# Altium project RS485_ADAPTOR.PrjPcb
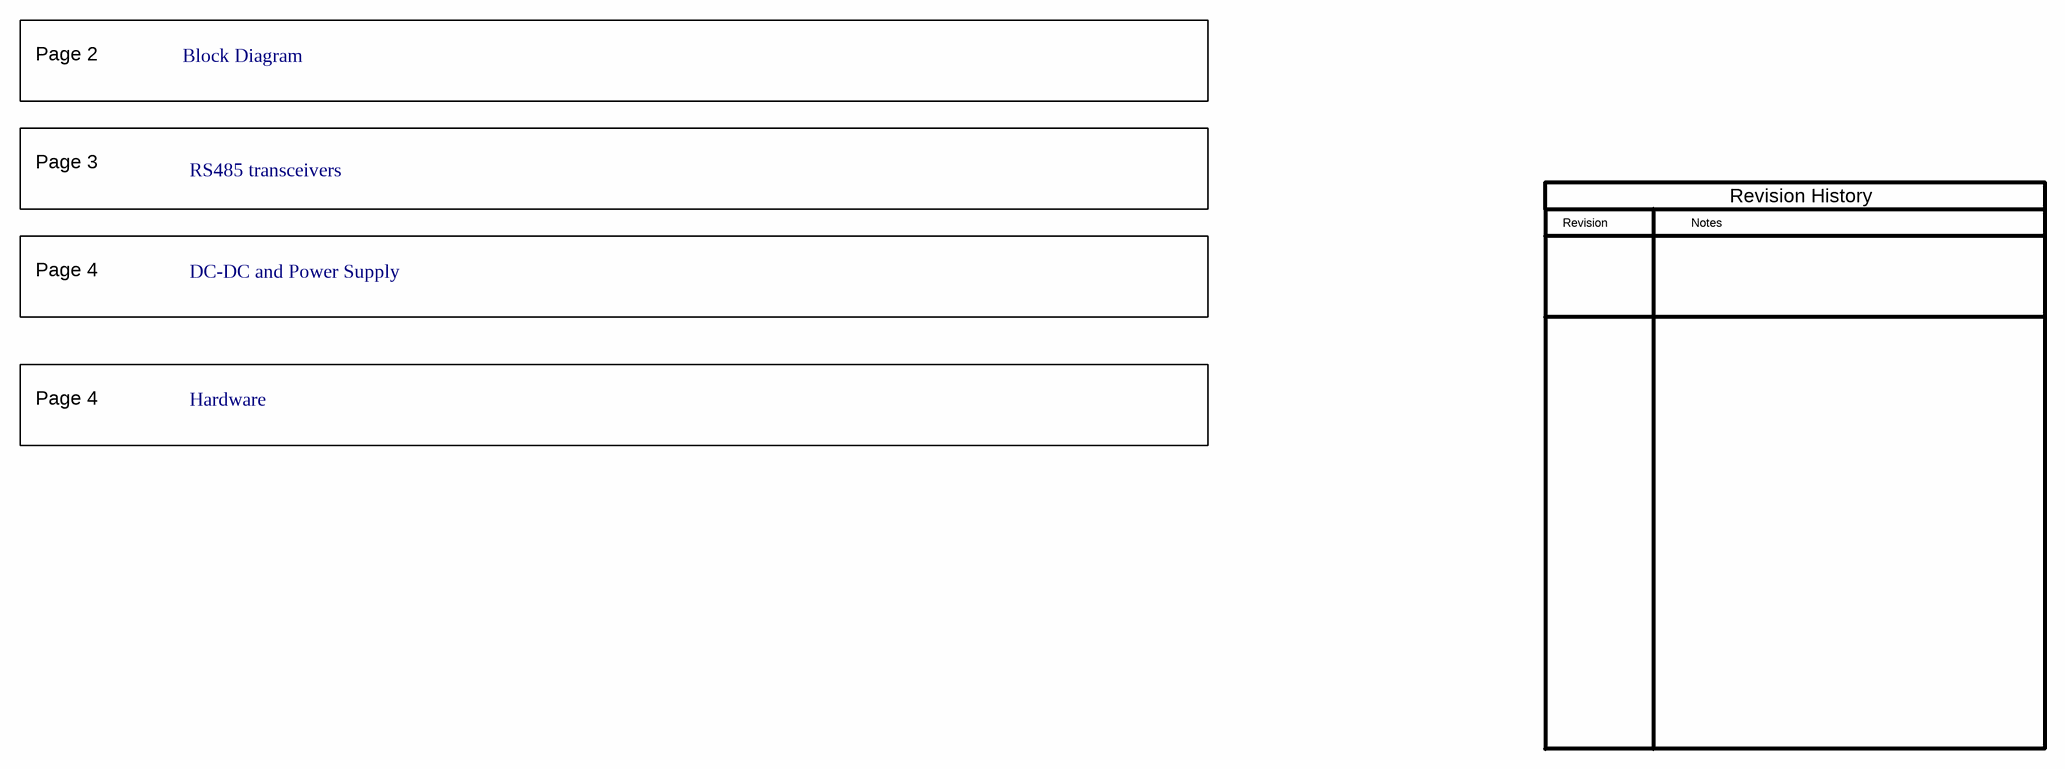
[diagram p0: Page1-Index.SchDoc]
TechSupport: http://www.ti.com/support; SCH_Rev: E2; PRJ_Title: RS485_COMMS; PRJ_Number: TIDA-00308; PRJ_Engineer: Sreenivasa Kallikuppa; PRJ_Customer: Public Release; PCB_Rev: E2; CopyrightYear: 2014
5 sheets, 112 parts. Net scope: flat (ports and power ports of the same name join across sheets).
Board file: RS485_ADAPTOR_E2.PcbDoc
Sheets:
  Page1-Index.SchDoc
  Page2 Block Diagram.SchDoc
  Page3-RS485 Transceivers.SchDoc
  Page4-DC-DC and Power supply.SchDoc
  Page5-Hardware.SchDoc

## Sheet Page1-Index.SchDoc
size 431 x 279 mm; Date: Not shown in title block; ApprovedBy: Not shown in title block; CheckedBy: Not shown in title block; Author: Not shown in title block; CompanyName: Not shown in title block; Engineer: Not shown in title block; Organization: Not shown in title block; Address1: Not shown in title block; Address2: Not shown in title block; Address3: Not shown in title block; Address4: Not shown in title block; DocumentNumber: 1; Revision: Use project parameter SCH_Rev; SheetNumber: 1; SheetTotal: 5; PageSetup: Record=PageOptions|CenterHorizontal=True|CenterVertical=True|PrintScale=0.62|XCorrection=1.00|YCorrection=1.00|PrintKind=0|BorderSize=5000000|LeftOffset=0|BottomOffset=0|Orientation=2|PaperLength=1000|PaperWidth=1000|Scale=100|PaperSource=15|PrintQuality=600|MediaType=1|DitherType=10|PaperKind=Letter|PrintScaleMode=1

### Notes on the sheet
- Page 2
- Block Diagram
- Page 3
- RS485 transceivers
- Revision
- Notes
- Revision History
- Page 4
- DC-DC and Power Supply
- Hardware

## Sheet Page2 Block Diagram.SchDoc
size 431 x 279 mm; Date: Not shown in title block; ApprovedBy: Not shown in title block; CheckedBy: Not shown in title block; Author: Not shown in title block; CompanyName: Not shown in title block; Engineer: Not shown in title block; Organization: Not shown in title block; Address1: Not shown in title block; Address2: Not shown in title block; Address3: Not shown in title block; Address4: Not shown in title block; DocumentNumber: 2; Revision: Use project parameter SCH_Rev; SheetNumber: 2; SheetTotal: 5; PageSetup: Record=PageOptions|CenterHorizontal=True|CenterVertical=True|PrintScale=1.00|XCorrection=1.00|YCorrection=1.00|PrintKind=0|BorderSize=5000000|LeftOffset=0|BottomOffset=0|Orientation=2|PaperLength=1000|PaperWidth=1000|Scale=100|PaperSource=15|PrintQuality=600|MediaType=1|DitherType=10|PaperKind=Letter|PrintScaleMode=1
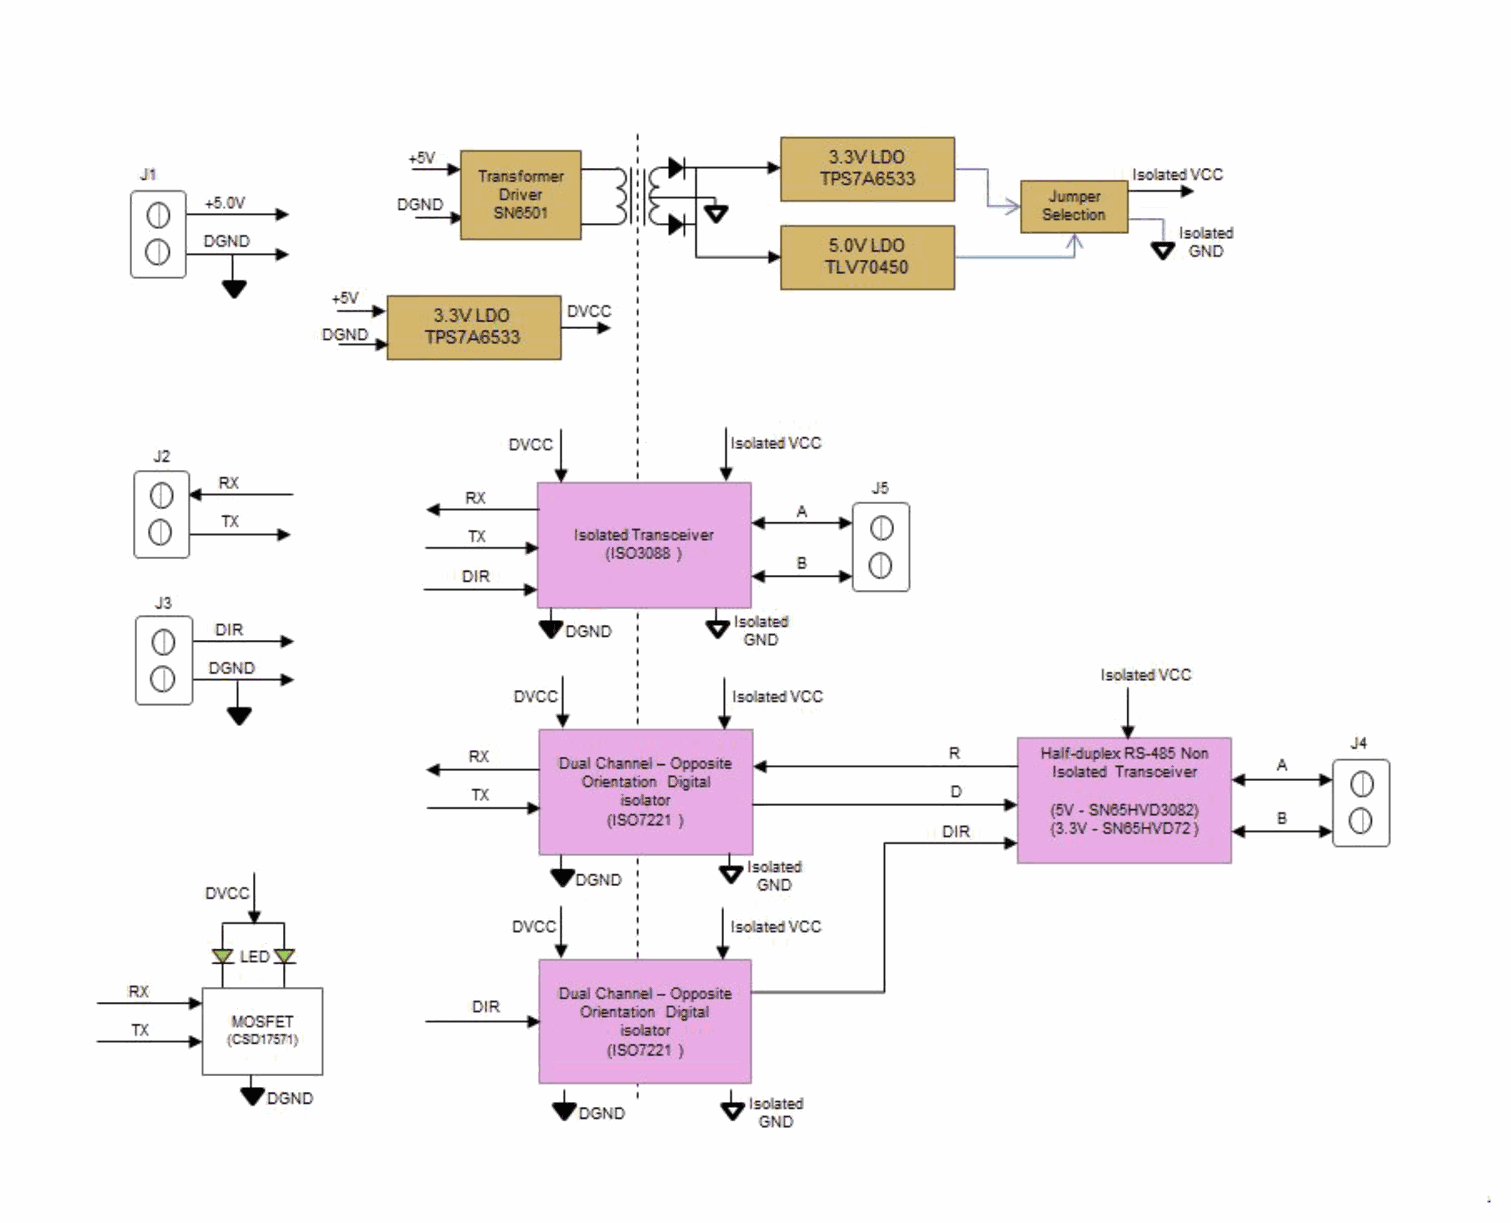
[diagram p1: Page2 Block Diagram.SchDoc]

## Sheet Page3-RS485 Transceivers.SchDoc
size 431 x 279 mm; Date: Not shown in title block; ApprovedBy: Not shown in title block; CheckedBy: Not shown in title block; Author: Not shown in title block; CompanyName: Not shown in title block; Engineer: Not shown in title block; Organization: Not shown in title block; Address1: Not shown in title block; Address2: Not shown in title block; Address3: Not shown in title block; Address4: Not shown in title block; DocumentNumber: 3; Revision: Use project parameter SCH_Rev; SheetNumber: 3; SheetTotal: 5; PageSetup: Record=PageOptions|CenterHorizontal=True|CenterVertical=True|PrintScale=0.62|XCorrection=1.00|YCorrection=1.00|PrintKind=0|BorderSize=5000000|LeftOffset=0|BottomOffset=0|Orientation=2|PaperLength=1000|PaperWidth=1000|Scale=100|PaperSource=15|PrintQuality=600|MediaType=1|DitherType=10|PaperKind=Letter|PrintScaleMode=1
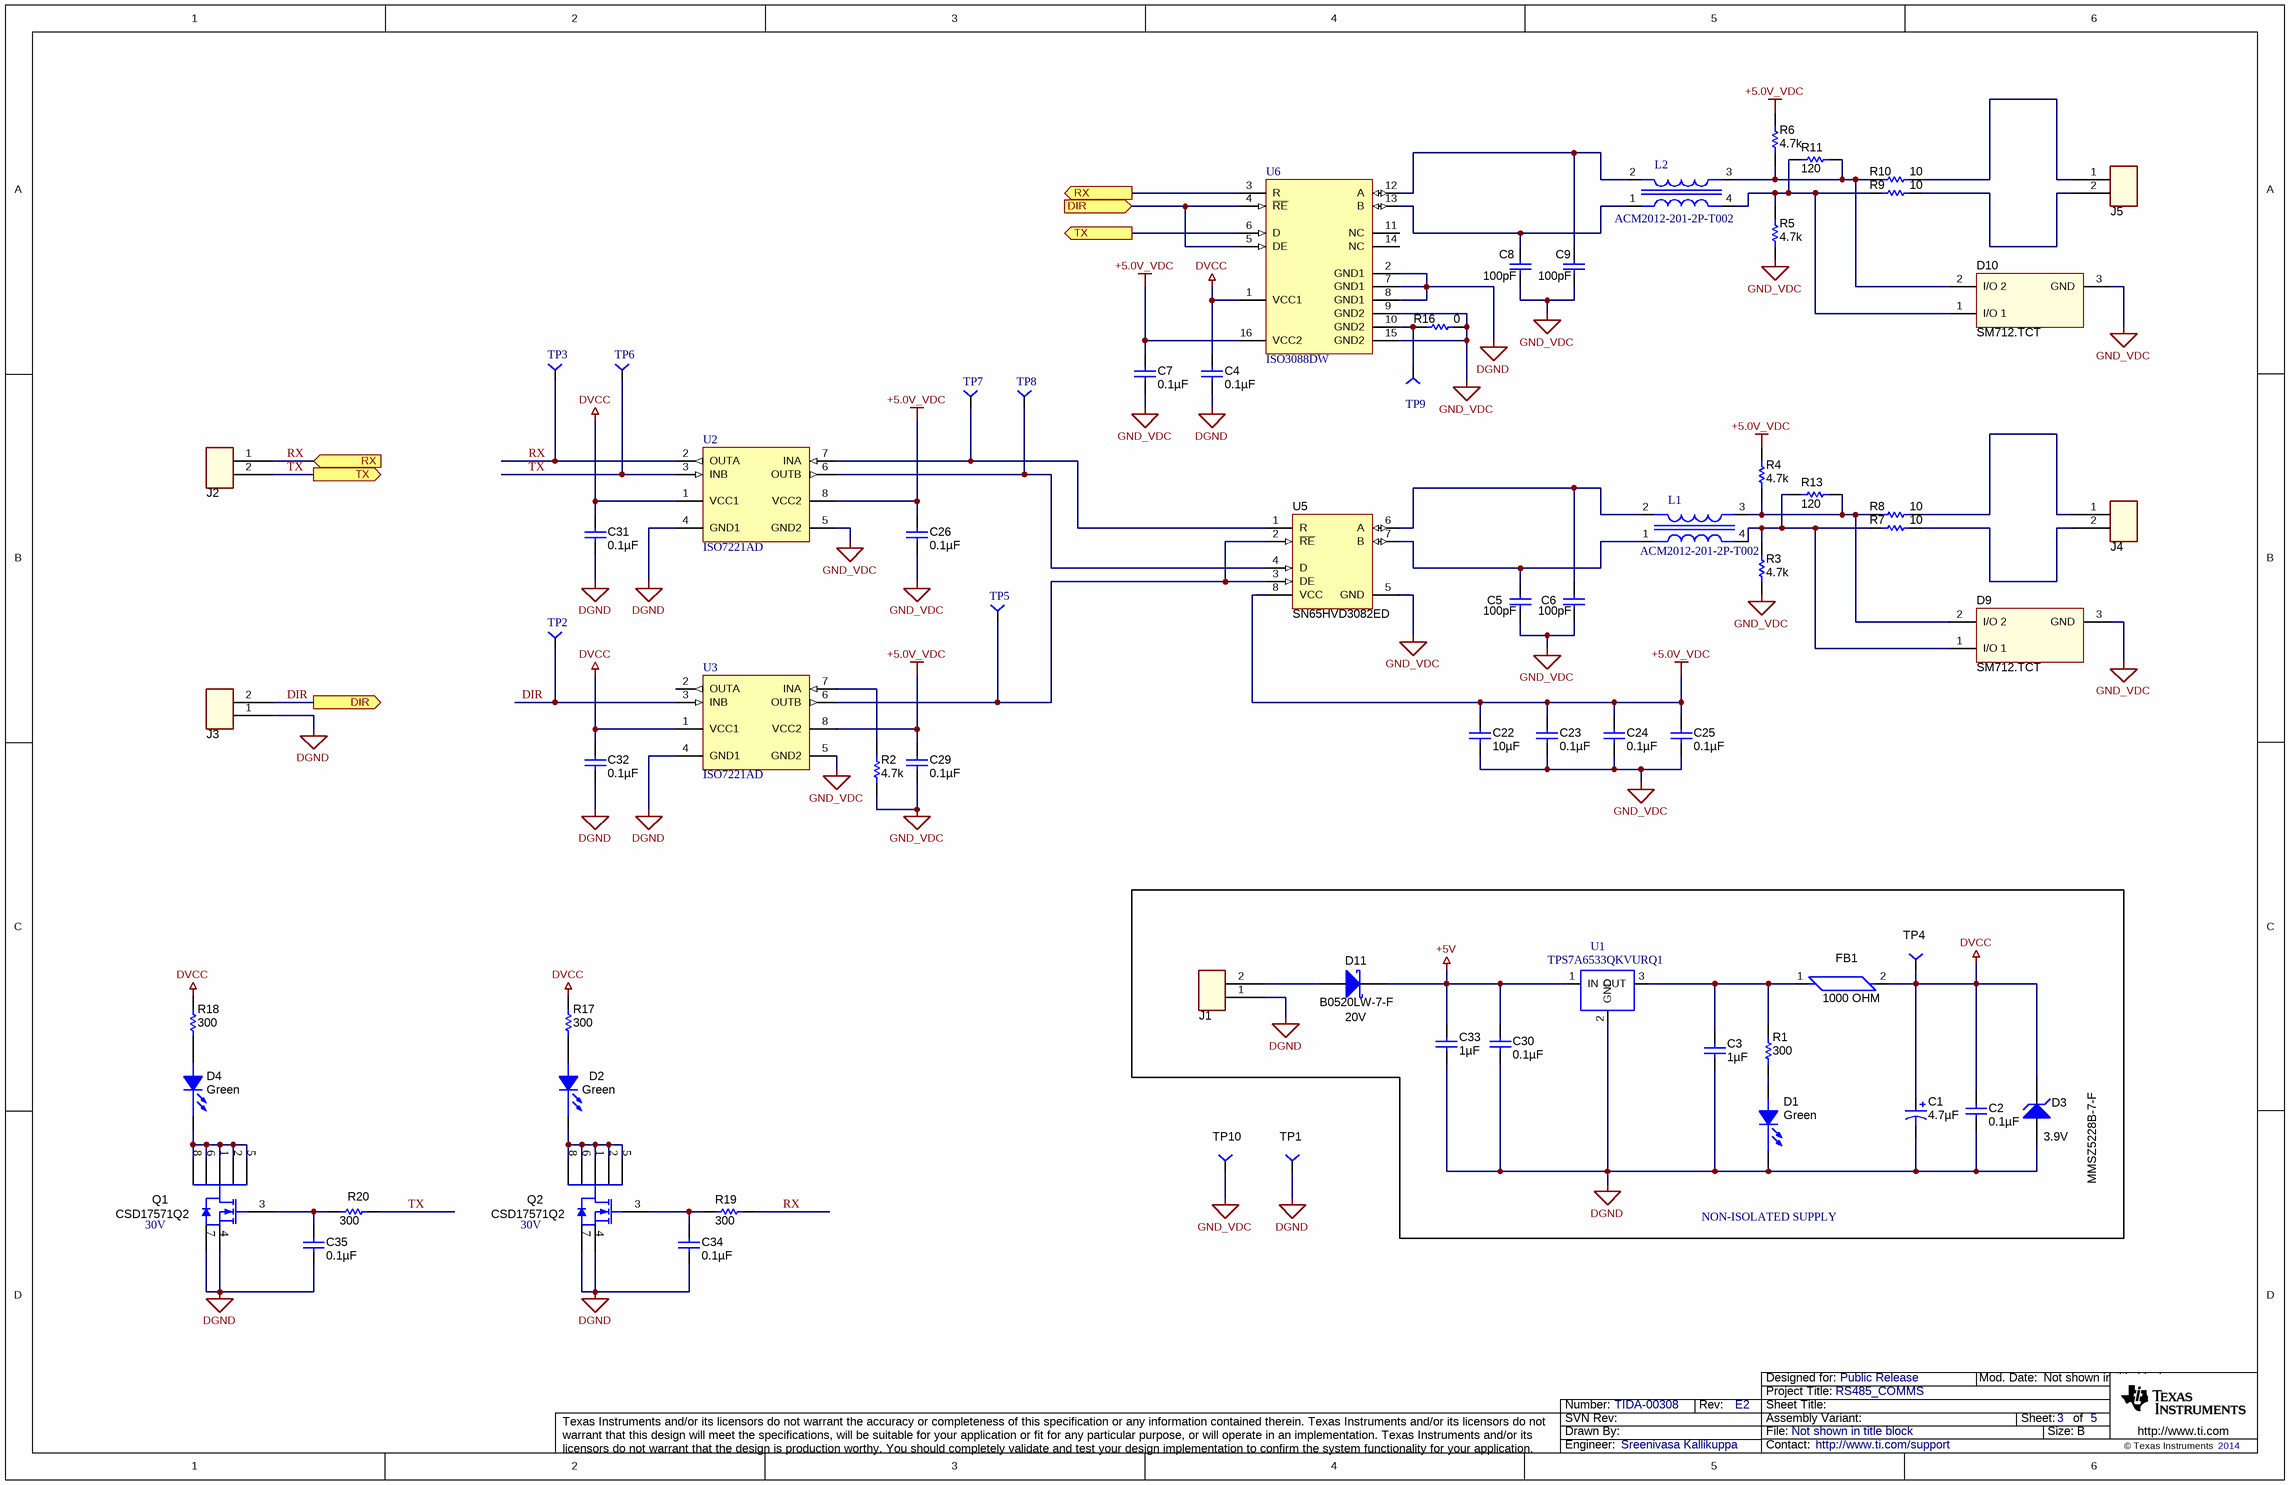
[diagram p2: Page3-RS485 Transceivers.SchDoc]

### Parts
C1  ValueDisplayed: 4.7µF  [6032-28]  (hidden comment: 293D475X9035C2TE3)
C2  ValueDisplayed: 0.1µF  [0603]  (hidden comment: C0603C104K5RACTU)
C3  ValueDisplayed: 1µF  [0603]  (hidden comment: C1608X7R1C105K)
C4  ValueDisplayed: 0.1µF  [0805_HV]  (hidden comment: 08055C104KAT2A)
C5  ValueDisplayed: 100pF  [0805_HV]  (hidden comment: 08055A101JAT2A)
C6  ValueDisplayed: 100pF  [0805_HV]  (hidden comment: 08055A101JAT2A)
C7  ValueDisplayed: 0.1µF  [0805_HV]  (hidden comment: 08055C104KAT2A)
C8  ValueDisplayed: 100pF  [0805_HV]  (hidden comment: 08055A101JAT2A)
C9  ValueDisplayed: 100pF  [0805_HV]  (hidden comment: 08055A101JAT2A)
C22  ValueDisplayed: 10µF  [0603]  (hidden comment: C0603C106M9PACTU)
C23  ValueDisplayed: 0.1µF  [0603]  (hidden comment: 06033C104JAT2A)
C24  ValueDisplayed: 0.1µF  [0603]  (hidden comment: 06033C104JAT2A)
C25  ValueDisplayed: 0.1µF  [0603]  (hidden comment: 06033C104JAT2A)
C26  ValueDisplayed: 0.1µF  [0805_HV]  (hidden comment: 08055C104KAT2A)
C29  ValueDisplayed: 0.1µF  [0805_HV]  (hidden comment: 08055C104KAT2A)
C30  ValueDisplayed: 0.1µF  [0603]  (hidden comment: C0603C104K5RACTU)
C31  ValueDisplayed: 0.1µF  [0805_HV]  (hidden comment: 08055C104KAT2A)
C32  ValueDisplayed: 0.1µF  [0805_HV]  (hidden comment: 08055C104KAT2A)
C33  ValueDisplayed: 1µF  [0603]  (hidden comment: C1608X7R1C105K)
C34  ValueDisplayed: 0.1µF  [0603]  (hidden comment: 06033C104JAT2A)
C35  ValueDisplayed: 0.1µF  [0603]  (hidden comment: 06033C104JAT2A)
D1  value Green  [LED0603AA]  (hidden comment: LED_LG L29K-G2J1-24-Z)
D2  value Green  [LED0603AA]  (hidden comment: LED_LG L29K-G2J1-24-Z)
D3  MMSZ5228B-7-F  value 3.9V  [sod-123]
D4  value Green  [LED0603AA]  (hidden comment: LED_LG L29K-G2J1-24-Z)
D9  SM712.TCT  [SM712.TCT]
D10  SM712.TCT  [SM712.TCT]
D11  B0520LW-7-F  value 20V  [SOD-123]
FB1  1000 OHM  [0603]
J1  CON-OSTVN02A150  [CN2_MTB_P100_PD80_D1.1_S5.54X6.5_STACK]  (value not drawn)
J2  CON-OSTVN02A150  [CN2_MTB_P100_PD80_D1.1_S5.54X6.5_STACK]  (value not drawn)
J3  CON-OSTVN02A150  [CN2_MTB_P100_PD80_D1.1_S5.54X6.5_STACK]  (value not drawn)
J4  CON-OSTVN02A150  [CN2_MTB_P100_PD80_D1.1_S5.54X6.5_STACK]  (value not drawn)
J5  CON-OSTVN02A150  [CN2_MTB_P100_PD80_D1.1_S5.54X6.5_STACK]  (value not drawn)
L1  ACM2012-201-2P-T002  [IND_0805-4P]
L2  ACM2012-201-2P-T002  [IND_0805-4P]
Q1  CSD17571Q2  value 30V  [SON_CSD17571Q2]
Q2  CSD17571Q2  value 30V  [SON_CSD17571Q2]
R1  value 300  [0603]  (hidden comment: CRCW0603300RJNEA)
R2  value 4.7k  [0603]  (hidden comment: CRCW06034K70JNEA)
R3  value 4.7k  [0603]  (hidden comment: CRCW06034K70JNEA)
R4  value 4.7k  [0603]  (hidden comment: CRCW06034K70JNEA)
R5  value 4.7k  [0603]  (hidden comment: CRCW06034K70JNEA)
R6  value 4.7k  [0603]  (hidden comment: CRCW06034K70JNEA)
R7  value 10  [2512M]  (hidden comment: ERJ-1TYJ100U)
R8  value 10  [2512M]  (hidden comment: ERJ-1TYJ100U)
R9  value 10  [2512M]  (hidden comment: ERJ-1TYJ100U)
R10  value 10  [2512M]  (hidden comment: ERJ-1TYJ100U)
R11  value 120  [1206]  (hidden comment: RC1206FR-07120RL)
R13  value 120  [1206]  (hidden comment: RC1206FR-07120RL)
R16  value 0  [0603]  (hidden comment: CRCW06030000Z0EA)
R17  value 300  [0603]  (hidden comment: CRCW0603300RJNEA)
R18  value 300  [0603]  (hidden comment: CRCW0603300RJNEA)
R19  value 300  [0603]  (hidden comment: CRCW0603300RJNEA)
R20  value 300  [0603]  (hidden comment: CRCW0603300RJNEA)
TP1  TP-040_RND  [TP-040_RND]  (value not drawn)
TP2  TP-040_RND  [TP-040_RND]  (value not drawn)
TP3  TP-040_RND  [TP-040_RND]  (value not drawn)
TP4  TP-040_RND  [TP-040_RND]  (value not drawn)
TP5  TP-040_RND  [TP-040_RND]  (value not drawn)
TP6  TP-040_RND  [TP-040_RND]  (value not drawn)
TP7  TP-040_RND  [TP-040_RND]  (value not drawn)
TP8  TP-040_RND  [TP-040_RND]  (value not drawn)
TP9  TP-040_RND  [TP-040_RND]  (value not drawn)
TP10  TP-040_RND  [TP-040_RND]  (value not drawn)
U1  TPS7A6533QKVURQ1  [KVU_1]
U2  ISO7221AD  [D0008A_N]
U3  ISO7221AD  [D0008A_N]
U5  SN65HVD3082ED  [D0008A_N]
U6  ISO3088DW  [DW0016A_N]

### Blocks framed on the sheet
NON-ISOLATED SUPPLY: C1-C3 C30 C33 D1 D3 D11 FB1 J1 R1 TP4 U1

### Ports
DIR (in), DIR (out), RX (in), RX (out), TX (out)

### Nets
+5.0V_VDC: C7.1 C22.1 C23.1 C24.1 C25.1 C26.1 C29.1 R4.2 R6.2 U2.8(VCC2) U3.8(VCC2) U5.8(VCC) U6.16(VCC2)
+5V: C30.1 C33.1 D11.1(K) U1.1(IN)
DGND: C1.2(-) C2.2 C3.2 C4.2 C30.2 C31.2 C32.2 C33.2 C34.2 C35.2 D1.1(C) D3.2(A) J1.1 J3.1 Q1.4(S) Q1.7(S) Q2.4(S) Q2.7(S) TP1.1 U1.2(GND) U2.4(GND1) U3.4(GND1) U6.2(GND1) U6.7(GND1) U6.8(GND1)
DVCC: C1.1(+) C2.1 C4.1 C31.1 C32.1 D3.1(K) FB1.2 R17.2 R18.2 TP4.1 U2.1(VCC1) U3.1(VCC1) U6.1(VCC1)
GND_VDC: C5.2 C6.2 C7.2 C8.2 C9.2 C22.2 C23.2 C24.2 C25.2 C26.2 C29.2 D9.3(GND) D10.3(GND) R2.1 R3.1 R5.1 R16.2 TP10.1 U2.5(GND2) U3.5(GND2) U5.5(GND) U6.9(GND2) U6.15(GND2)
DIR: J3.2 TP2.1 U3.3(INB) U6.4(~{RE}) U6.5(DE) ; port DIR
RX: J2.1 R19.1 TP3.1 U2.2(OUTA) U6.3(R) ; port RX
TX: J2.2 R20.1 TP6.1 U2.3(INB) U6.6(D) ; port TX
NetC3_1: C3.1 FB1.1 R1.2 U1.3(OUT)
NetC5_1: C5.1 L1.1 U5.7(B)
NetC6_1: C6.1 L1.2 U5.6(A)
NetC8_1: C8.1 L2.1 U6.13(B)
NetC9_1: C9.1 L2.2 U6.12(A)
NetC34_1: C34.1 Q2.3(G) R19.2
NetC35_1: C35.1 Q1.3(G) R20.2
NetD1_2: D1.2(A) R1.1
NetD2_1: D2.1(C) Q2.1(D) Q2.2(D) Q2.5(D) Q2.6(D) Q2.8(D)
NetD2_2: D2.2(A) R17.1
NetD4_1: D4.1(C) Q1.1(D) Q1.2(D) Q1.5(D) Q1.6(D) Q1.8(D)
NetD4_2: D4.2(A) R18.1
NetD9_1: D9.1(I/O_1) L1.4 R3.2 R7.1 R13.2
NetD9_2: D9.2(I/O_2) L1.3 R4.1 R8.1 R13.1
NetD10_1: D10.1(I/O_1) L2.4 R5.2 R9.1 R11.2
NetD10_2: D10.2(I/O_2) L2.3 R6.1 R10.1 R11.1
NetD11_2: D11.2(A) J1.2
NetJ4_1: J4.1 R8.2
NetJ4_2: J4.2 R7.2
NetJ5_1: J5.1 R10.2
NetJ5_2: J5.2 R9.2
NetR2_2: R2.2 U3.7(INA)
NetR16_1: R16.1 TP9.1 U6.10(GND2)
NetTP5_1: TP5.1 U3.6(OUTB) U5.2(~{RE}) U5.3(DE)
NetTP7_1: TP7.1 U2.7(INA) U5.1(R)
NetTP8_1: TP8.1 U2.6(OUTB) U5.4(D)

Not connected (* = marked no-connect by the designer): U3 2(OUTA); U6 11(NC) 14(NC)

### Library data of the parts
C1 = 293D475X9035C2TE3: CAP, TA, 4.7uF, 35V, +/-10%, 1.9 ohm, SMD; Manufacturer: Vishay-Sprague; Polarized: Y; CompType: Capacitor; U/M: EA; Cap_F: 0.0000047; Tolerance_%: 10; Value1: 1.9 ohm; VDC_V: 35; ESR_Ohm: 1.9; IRMS_A: 0.24; TaMin_C: -55; TaMax_C: 125; Cap_Case: C
C2 C30 = C0603C104K5RACTU: CAP, CERM, 0.1uF, 50V, +/-10%, X7R, 0603; Manufacturer: Kemet; Polarized: N; CompType: Capacitor; U/M: EA; Cap_F: 0.0000001; Tolerance_%: 10; Value1: Unknown; VDC_V: 50; TaMin_C: -55; TaMax_C: 125
C3 C33 = C1608X7R1C105K: CAP, CERM, 1uF, 16V, +/-10%, X7R, 0603; Manufacturer: TDK; Polarized: N; CompType: Capacitor; U/M: EA; Cap_F: 0.000001; Tolerance_%: 10; ESR_Ohm: 0.0057; Value1: 0.0057 ohm; VDC_V: 16; TaMin_C: -55; TaMax_C: 125
C4 C7 C26 C29 C31 C32 = 08055C104KAT2A: CAP, CERM, 0.1uF, 50V, +/-10%, X7R, 0805; Manufacturer: AVX; Polarized: N; CompType: Capacitor; U/M: EA; Cap_F: 0.0000001; Tolerance_%: 10; ESR_Ohm: 0.024; Value1: 0.024 ohm; VDC_V: 50; TaMin_C: -55; TaMax_C: 125; Cap_Case: 0805
C5 C6 C8 C9 = 08055A101JAT2A: CAP, CERM, 100pF, 50V, +/-5%, C0G/NP0, 0805; Manufacturer: AVX; Polarized: N; CompType: Capacitor; U/M: EA; Cap_F: 0.0000000001; Tolerance_%: 5; ESR_Ohm: 0.356; Value1: 0.356 ohm; VDC_V: 50; TaMin_C: -55; TaMax_C: 125; Cap_Case: 0805
C22 = C0603C106M9PACTU: CAP, CERM, 10uF, 6.3V, +/-20%, X5R, 0603; Manufacturer: Kemet; Polarized: N; CompType: Capacitor; U/M: EA; Cap_F: 0.00001; Tolerance_%: 20; ESR_Ohm: 0.004; Value1: 0.004 ohm; VDC_V: 6.3; IRMS_A: 8.9; TaMin_C: -55; TaMax_C: 85
C23-C25 C34 C35 = 06033C104JAT2A: CAP, CERM, 0.1uF, 25V, +/-5%, X7R, 0603; Manufacturer: AVX; Polarized: N; CompType: Capacitor; U/M: EA; Cap_F: 0.0000001; Tolerance_%: 5; ESR_Ohm: 0.05; Value1: 0.05 ohm; VDC_V: 25; TaMin_C: -55; TaMax_C: 125
D1 D2 D4 = LED_LG L29K-G2J1-24-Z: LED SmartLED Green 570NM; Manufacturer: OSRAM; SymbolCreator: x0120606
D3 = 1SMB5915BT3G: DIODE ZENER 3.9V 500MW SOD123; Manufacturer: Diodes Incorporated; U/M: EA; Power_W: 0.55; Vz_V: 3.9; Value1: 0.55W; RJA_CperW: 226
D9 D10 = SM712.TCT: IC TVS ASYMM RS-485V 7/12V SOT23; Manufacturer: Semtech; Voltage - Reverse Standoff (Typ): 12V; Voltage - Breakdown: 13.3V; Power_W: 400W; Polarization: 2 Channel Array - Bidirectional
D11 = MBR0520LT1G: Diode, Schottky, 20V, 0.5A, SOD-123; Manufacturer: Diodes Inc; U/M: EA; Vf_V: 0.385; Value2: 0.385V; Io_A: 0.5; Vr_V: 20; TJmax_C: 125; RJC_CperW: 150
FB1 = MMZ1608B102C: FERRITE CHIP 1000 OHM 300MA 0603; Manufacturer: TDK Corporation; CompType: Ferrite Bead
J1 = CON-OSTVN02A150: CONN TERM BLOCK 2.54MM 2POS PCB; Manufacturer: On Shore Technology Inc; SymbolCreator: x0120606; CompType: Terminal Block
J2-J5 = CON-OSTVN02A150: Terminal Block, 4x1, 2.54mm, TH; Manufacturer: On Shore Technology Inc; SymbolCreator: x0120606
L1 L2 = IND_ACM2012_SERIES: CHOKE COMM MODE 200 OHM .35A SMD; Manufacturer: TDK; Area: 8.13 mm; Value: xx uH
Q1 Q2 = CSD17571Q2: MOSFET, N-CH, 30V, 22A, SON 2X2 MM; Manufacturer: TEXAS INSTRUMENTS; CompType: POWER MOSFET
R1 R17-R20 = CRCW0603300RJNEA: RES, 300 ohm, 5%, 0.1W, 0603; Manufacturer: Vishay-Dale; CompType: Resistor; Value_Code: 300R; Tolerance_%: 5; Power_W: 0.1; VDC_V: 75; TempCo: 200 ppm/C; EIA_Code: E24; U/M: EA
R2-R6 = CRCW06034K70JNEA: RES, 4.7k ohm, 5%, 0.1W, 0603; Manufacturer: Vishay-Dale; CompType: Resistor; Res_ohm: 4700; Value_Code: 4k70; Tolerance_%: 5; Power_W: 0.1; VDC_V: 75; TempCo: 200 ppm/C; EIA_Code: E24; U/M: EA
R7-R10 = ERJ-1TYJ100U: RES, 10 ohm, 5%, 1W, 2512; Manufacturer: Panasonic; CompType: Resistor; Value_Code: 10R0; Tolerance_%: 5; Power_W: 1; VDC_V: 200; TempCo: 200 ppm/C; EIA_Code: E24; U/M: EA
R11 R13 = RC1206FR-07120RL: RES, 120 ohm, 1%, 0.25W, 1206; Manufacturer: Yageo America; CompType: Resistor; Value_Code: 120R; Tolerance_%: 1; Power_W: 0.25; VDC_V: 200; TempCo: 100 ppm/C; U/M: EA
R16 = CRCW06030000Z0EA: RES, 0 ohm, 5%, 0.1W, 0603; Manufacturer: Vishay-Dale; CompType: Resistor; Value_Code: 0000; Tolerance_%: 5; Power_W: 0.1; VDC_V: 75; TempCo: 200 ppm/C; EIA_Code: E24; U/M: EA
TP1-TP10 = TP-040_RND: Test Point, O.040 Hole; Manufacturer: STD; Value: STD
U1 = TPS7A6533QKVURQ1: IC, 300-mA 40-V LOW-DROPOUT REGULATOR WITH 25-uA QUIESCENT CURRENT; Manufacturer: TI; Alternate Manufacturer: None; Area: 136210
U2 U3 = ISO7221AD: 1 Mbps Dual Channels, 1 / 1, Digital Isolator, 3.3 V / 5 V, -40 to +125 degC, 8-pin SOIC (D), Green (RoHS & no Sb/Br); Manufacturer: Texas Instruments; Alternate Manufacturer: None; Alternate PartNumber: Equivalent; Datarate(Mbps): 1; Input Noise Filter: Yes; Insulation Rating(VRMS): 2500; Prop Delay(Max)(ns): 475; Rating: Catalog; Supply Voltage(s)(V): 3.3, 5; TTL/CMOS Input Threshold: TTL
U5 = SN65HVD3082ED: IC, RS485 TRANSCEIVER LP, 8-SOIC; Manufacturer: TEXAS INSTRUMENTS; CompType: LOW-POWER RS-485 TRANSCEIVER; SymbolCreator: x0199378
U6 = ISO3088DW: Isolated RS-485 Transceiver, 20 Mbps, 5 V, Half Duplex, -40 to 85 degC, 16-pin SOIC (DW); Manufacturer: Texas Instruments; Alternate Manufacturer: None; Alternate PartNumber: Equivalent; Eco-Plan: TBD; # of TX/RX: 1 TX / 1 RX; Drivers Per Package: 1; Isolated: Yes; Number of Nodes: 256; Signaling Rate(Mbps): 20; Common Mode Range: -7 to 12; ESD(kV): 16; Fault Protection(V): -9 to 14; Fail Safe: Idle, Open, Short; ICC(Max)(mA): 15; Supply Voltage(s)(V): 5; Rating: Catalog

## Sheet Page4-DC-DC and Power supply.SchDoc
size 431 x 279 mm; Date: Not shown in title block; ApprovedBy: Not shown in title block; CheckedBy: Not shown in title block; Author: Not shown in title block; CompanyName: Not shown in title block; Engineer: Not shown in title block; Organization: Not shown in title block; Address1: Not shown in title block; Address2: Not shown in title block; Address3: Not shown in title block; Address4: Not shown in title block; DocumentNumber: 4; Revision: Use project parameter SCH_Rev; SheetNumber: 4; SheetTotal: 5; PageSetup: Record=PageOptions|CenterHorizontal=True|CenterVertical=True|PrintScale=0.62|XCorrection=1.00|YCorrection=1.00|PrintKind=0|BorderSize=5000000|LeftOffset=0|BottomOffset=0|Orientation=2|PaperLength=1000|PaperWidth=1000|Scale=100|PaperSource=15|PrintQuality=600|MediaType=1|DitherType=10|PaperKind=Letter|PrintScaleMode=1
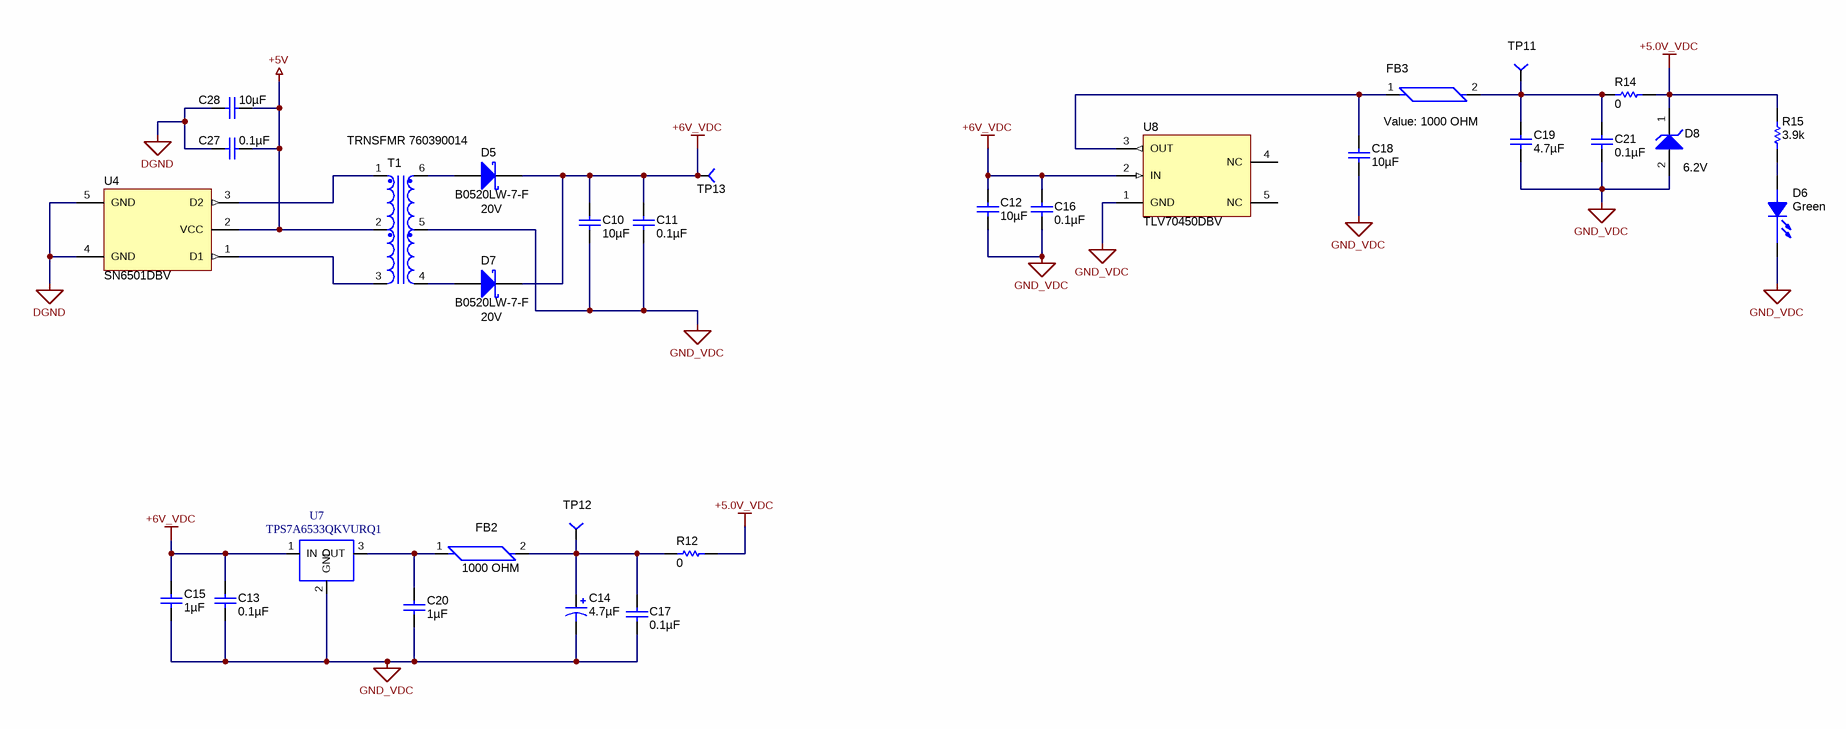
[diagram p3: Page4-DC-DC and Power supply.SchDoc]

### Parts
C10  ValueDisplayed: 10µF  [1210]
C11  ValueDisplayed: 0.1µF  [0603]
C12  ValueDisplayed: 10µF  [1210]
C13  ValueDisplayed: 0.1µF  [0603]  (hidden comment: C0603C104K5RACTU)
C14  ValueDisplayed: 4.7µF  [6032-28]  (hidden comment: 293D475X9035C2TE3)
C15  ValueDisplayed: 1µF  [0603]  (hidden comment: C1608X7R1C105K)
C16  ValueDisplayed: 0.1µF  [0603]
C17  ValueDisplayed: 0.1µF  [0603]  (hidden comment: C0603C104K5RACTU)
C18  ValueDisplayed: 10µF  [1210]
C19  ValueDisplayed: 4.7µF  [0805_HV]
C20  ValueDisplayed: 1µF  [0603]  (hidden comment: C1608X7R1C105K)
C21  ValueDisplayed: 0.1µF  [0603]
C27  ValueDisplayed: 0.1µF  [0603]
C28  ValueDisplayed: 10µF  [1210]
D5  B0520LW-7-F  value 20V  [SOD-123]
D6  value Green  [LED0603AA]
D7  B0520LW-7-F  value 20V  [SOD-123]
D8  value 6.2V  [powerDI123]
FB2  1000 OHM  [0603]
FB3  value 1000 OHM  [FB0603]
R12  value 0  [0603]  (hidden comment: CRCW06030000Z0EA)
R14  value 0  [0603]  (hidden comment: CRCW06030000Z0EA)
R15  value 3.9k  [0603]
T1  TRNSFMR 760390014  [760390015]
TP11  (no value)  [TP-040_RND]
TP12  TP-040_RND  [TP-040_RND]  (value not drawn)
TP13  TP-040_RND  [TP-040_RND]  (value not drawn)
U4  SN6501DBV  [DBV0005A_N]
U7  TPS7A6533QKVURQ1  [KVU_1]
U8  TLV70450DBV  [DBV0005A_N]

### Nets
+5.0V_VDC: D8.1(K) R12.2 R14.2 R15.2
+5V: C27.2 C28.2 T1.2 U4.2(VCC)
+6V_VDC: C10.1 C11.1 C12.2 C13.1 C15.1 C16.1 D5.1(K) D7.1(K) TP13.1 U7.1(IN) U8.2(IN)
DGND: C27.1 C28.1 U4.4(GND) U4.5(GND)
GND_VDC: C10.2 C11.2 C12.1 C13.2 C14.2(-) C15.2 C16.2 C17.2 C18.1 C19.1 C20.2 C21.2 D6.1(C) D8.2(A) T1.5 U7.2(GND) U8.1(GND)
NetC14_1: C14.1(+) C17.1 FB2.2 R12.1 TP12.1
NetC18_2: C18.2 FB3.1 U8.3(OUT)
NetC19_2: C19.2 C21.1 FB3.2 R14.1 TP11.1
NetC20_1: C20.1 FB2.1 U7.3(OUT)
NetD5_2: D5.2(A) T1.6
NetD6_2: D6.2(A) R15.1
NetD7_2: D7.2(A) T1.4
NetT1_1: T1.1 U4.3(D2)
NetT1_3: T1.3 U4.1(D1)

Not connected (* = marked no-connect by the designer): U8 4(NC) 5(NC)

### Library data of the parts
C10 C12 C18 C28 = GMK325AB7106MM-T: CAP, CERM, 10uF, 35V, +/-20%, X7R, 1210; Manufacturer: Taiyo Yuden; Polarized: N; CompType: Capacitor; U/M: EA; Cap_F: 0.00001; Tolerance_%: 20; Value1: Unknown; VDC_V: 35; TaMin_C: -55; TaMax_C: 125
C11 C13 C16 C17 C21 C27 = C0603C104K5RACTU: as C2 on sheet Page3-RS485 Transceivers
C14 = 293D475X9035C2TE3: as C1 on sheet Page3-RS485 Transceivers
C15 C20 = C1608X7R1C105K: as C3 on sheet Page3-RS485 Transceivers
C19 = C2012X5R1H475K125AB: CAP, CERM, 4.7uF, 50V, +/-10%, X5R, 0805; Manufacturer: TDK; Polarized: N; CompType: Capacitor; U/M: EA; Cap_F: 0.0000047; Tolerance_%: 10; Value1: Unknown; VDC_V: 50; TaMin_C: -55; TaMax_C: 85; Cap_Case: 0805
D5 D7 = MBR0520LT1G: as D11 on sheet Page3-RS485 Transceivers
D6 = LED_LG L29K-G2J1-24-Z: as D1 on sheet Page3-RS485 Transceivers
D8 = DFLZ6V2-7: Diode, Zener, 6.2V, 1W, PowerDI123; Manufacturer: Diodes Inc.; U/M: EA; Power_W: 1; Vz_V: 6.2; RJA_CperW: 110
FB2 FB3 = MMZ1608B102C: as FB1 on sheet Page3-RS485 Transceivers
R12 R14 = CRCW06030000Z0EA: as R16 on sheet Page3-RS485 Transceivers
R15 = CRCW06033K90JNEA: RES, 3.9k ohm, 5%, 0.1W, 0603; Manufacturer: Vishay-Dale; CompType: Resistor; Res_ohm: 3900; Value_Code: 3k90; Tolerance_%: 5; Power_W: 0.1; VDC_V: 75; TempCo: 200 ppm/C; EIA_Code: E24; U/M: EA
T1 = TRNSFMR 760390015: Transformer 475uH SMD; Manufacturer: Wurth Electronics Midcom
TP11-TP13 = TP-040_RND: as TP1 on sheet Page3-RS485 Transceivers
U4 = SN6501DBV: Transformer Driver for Isolated Power Supplies, DBV0005A; Alternate Manufacturer: None; Manufacturer: Texas Instruments; SymbolCreator: a0411947; CompType: IC; U/M: EA
U7 = TPS7A6533QKVURQ1: as U1 on sheet Page3-RS485 Transceivers
U8 = TLV70450DBV: Regulator, LDO, 5V, 0.15A, SOT23-5; Alternate Manufacturer: None; Manufacturer: Texas Instruments; SymbolCreator: x0120606; CompType: IC

## Sheet Page5-Hardware.SchDoc
size 431 x 279 mm; Date: Not shown in title block; ApprovedBy: Not shown in title block; CheckedBy: Not shown in title block; Author: Not shown in title block; CompanyName: Not shown in title block; Engineer: Not shown in title block; Organization: Not shown in title block; Address1: Not shown in title block; Address2: Not shown in title block; Address3: Not shown in title block; Address4: Not shown in title block; DocumentNumber: 5; Revision: E2; SheetNumber: 5; SheetTotal: 5; PageSetup: Record=PageOptions|CenterHorizontal=True|CenterVertical=True|PrintScale=1.00|XCorrection=1.00|YCorrection=1.00|PrintKind=0|BorderSize=5000000|LeftOffset=0|BottomOffset=0|Orientation=2|PaperLength=1000|PaperWidth=1000|Scale=100|PaperSource=15|PrintQuality=600|MediaType=1|DitherType=10|PaperKind=Letter|PrintScaleMode=1
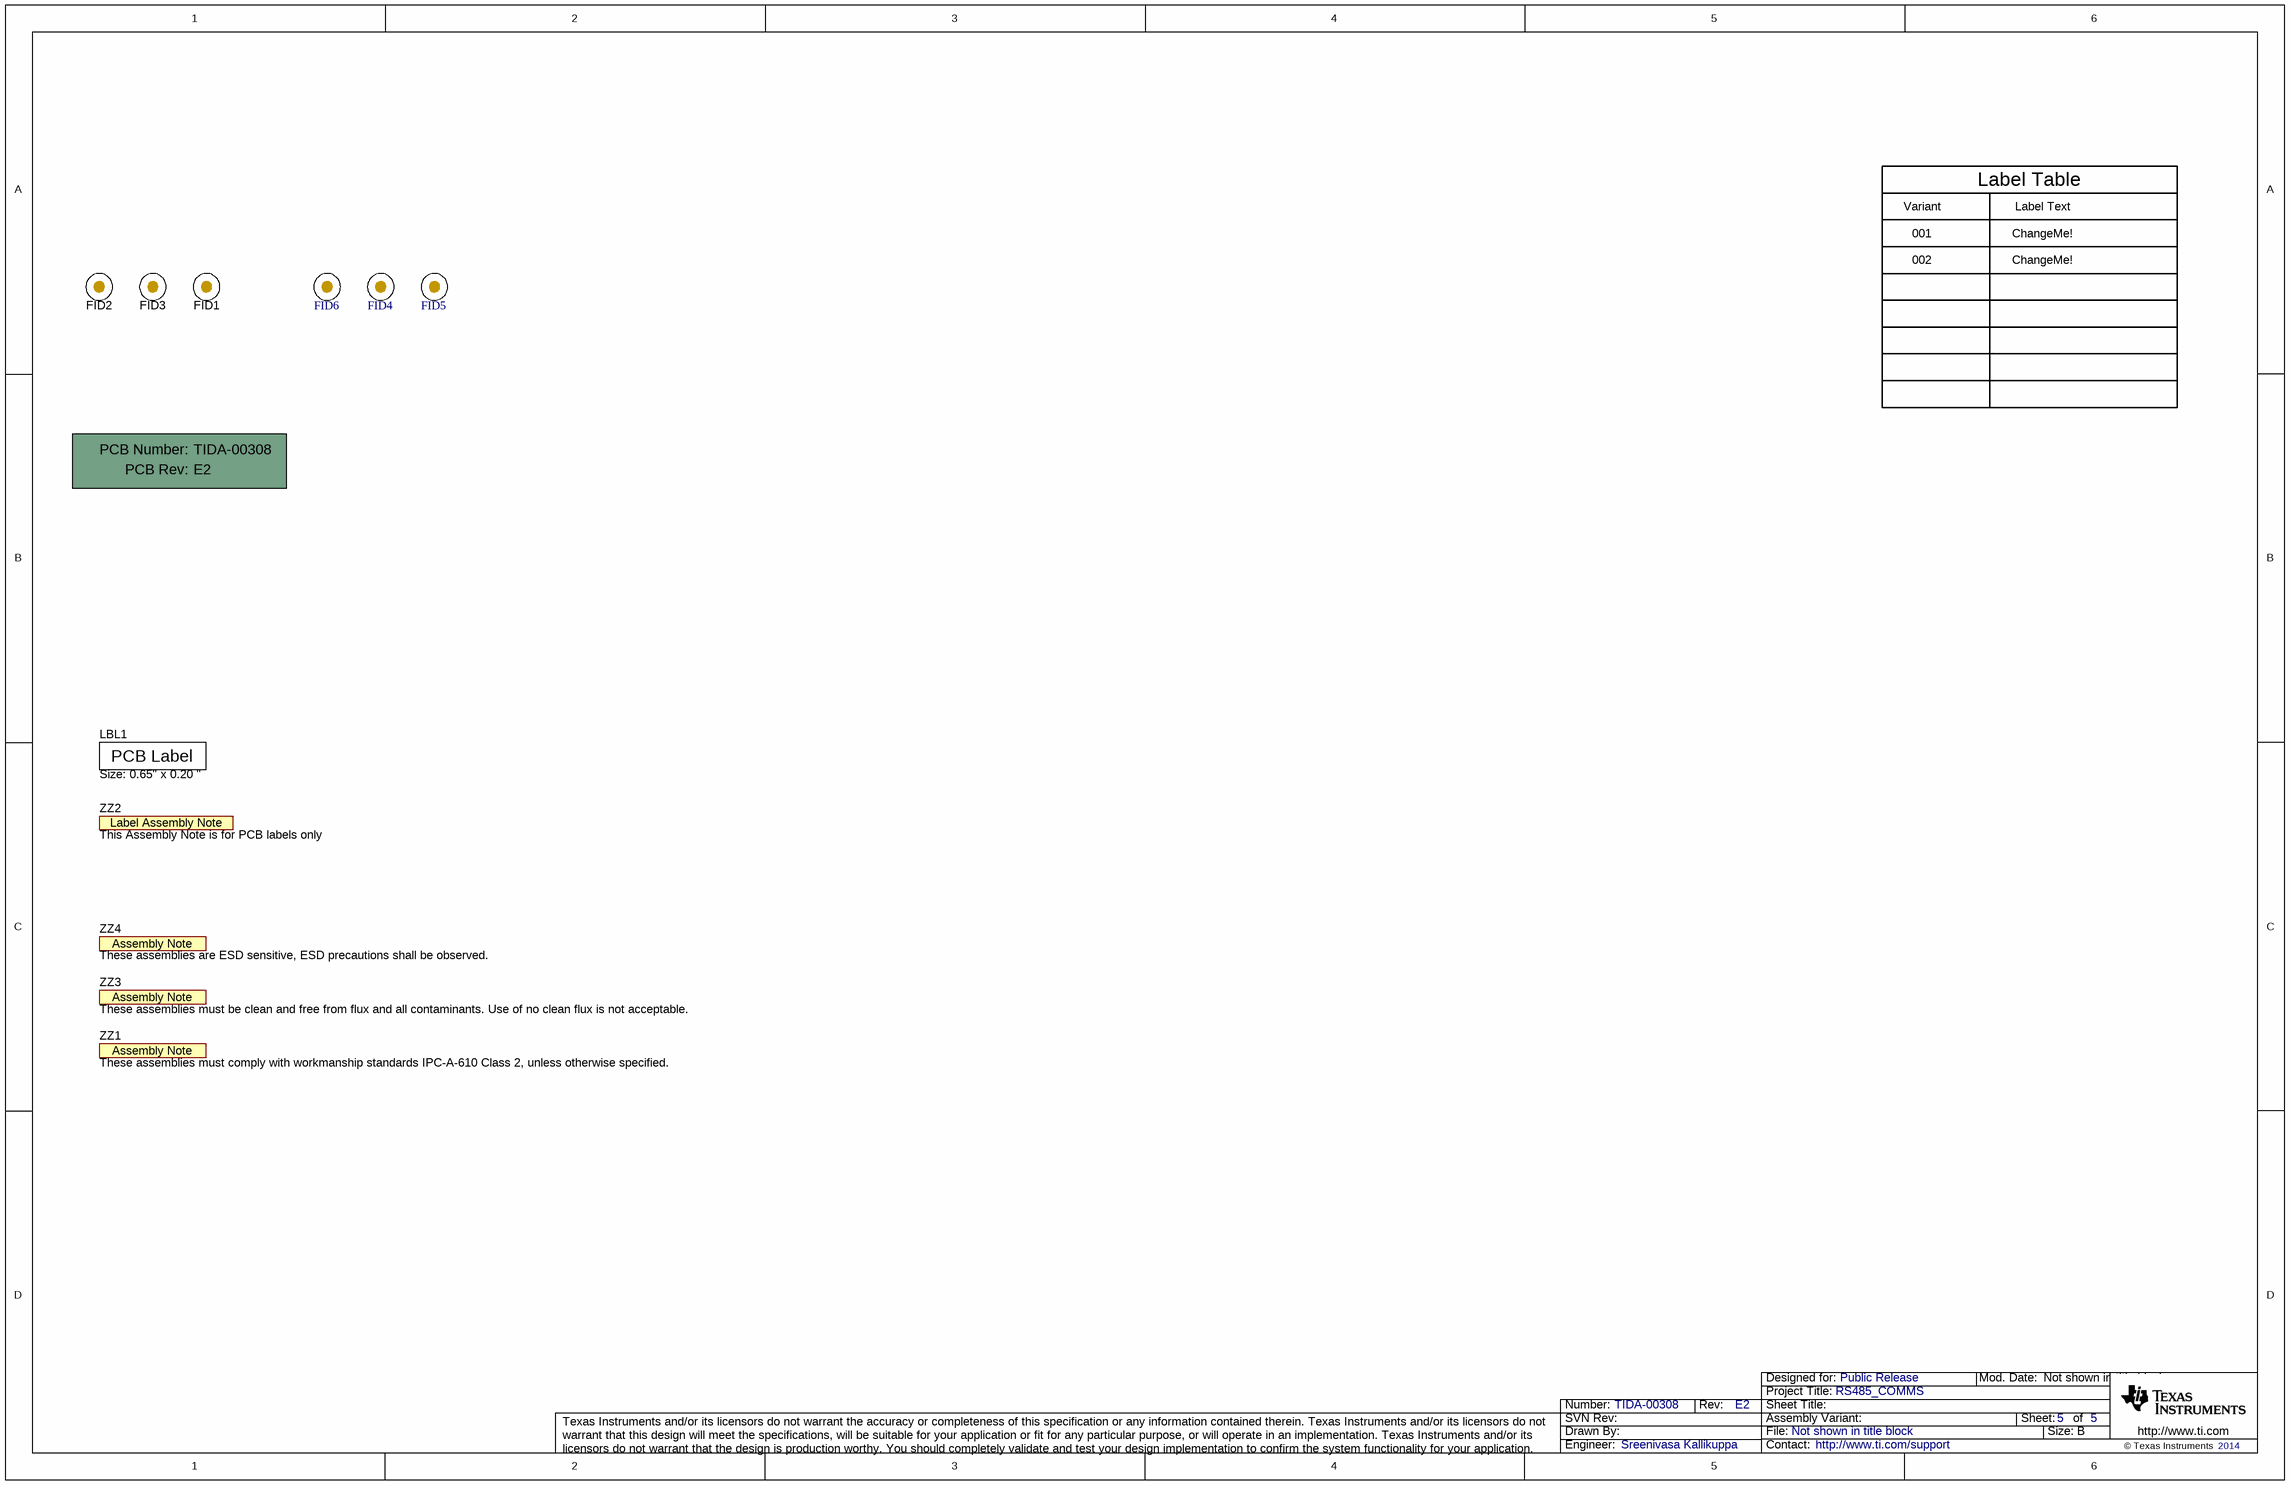
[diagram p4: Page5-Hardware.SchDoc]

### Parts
!PCB1  Printed Circuit Board  (value not drawn)  (mechanical)
FID1  Fiducial  [Fiducial10-20]  (value not drawn)
FID2  Fiducial  [Fiducial10-20]  (value not drawn)
FID3  Fiducial  [Fiducial10-20]  (value not drawn)
FID4  Fiducial  [Fiducial10-30]  (value not drawn)
FID5  Fiducial  [Fiducial10-30]  (value not drawn)
FID6  Fiducial  [Fiducial10-30]  (value not drawn)
LBL1  Size: 0.65" x 0.20 "  [Label_650x200]
ZZ1  These assemblies must comply with workmanship standards IPC-A-610 Class 2, unless otherwise specified.  [AssemblyNote]  (no BOM)
ZZ2  This Assembly Note is for PCB labels only  [AssemblyNoteLabel]  (no BOM)
ZZ3  These assemblies must be clean and free from flux and all contaminants. Use of no clean flux is not acceptable.  [AssemblyNote]  (no BOM)
ZZ4  These assemblies are ESD sensitive, ESD precautions shall be observed.  [AssemblyNote]  (no BOM)

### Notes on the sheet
- Variant
- 001
- Label Table
- Label Text
- ChangeMe!
- 002

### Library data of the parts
!PCB1 = PCB: Manufacturer: Any; PartNumber: TIDA-00308; SymbolCreator: a0412235
FID1-FID6 = Fiducial: Fiducial mark.  There is nothing to buy or mount.; SymbolCreator: codlsc
LBL1 = THT-14-423-10: Thermal Transfer Printable Labels, 0.650" W x 0.200" H - 10,000 per roll; Manufacturer: Brady; SymbolCreator: a0412235; CompType: Label
ZZ1 ZZ3 ZZ4 = AssemblyNote: SymbolCreator: codlsc
ZZ2 = AssemblyNoteLabel: SymbolCreator: a0412235

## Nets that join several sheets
+5.0V_VDC: Page3-RS485 Transceivers (13 pins), Page4-DC-DC and Power supply (D8.1 R12.2 R14.2 R15.2)
+5V: Page3-RS485 Transceivers (C30.1 C33.1 D11.1 U1.1), Page4-DC-DC and Power supply (C27.2 C28.2 T1.2 U4.2)
DGND: Page3-RS485 Transceivers (25 pins), Page4-DC-DC and Power supply (C27.1 C28.1 U4.4 U4.5)
GND_VDC: Page3-RS485 Transceivers (23 pins), Page4-DC-DC and Power supply (17 pins)

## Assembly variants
001: not fitted C34 C35 FID1 FID2 FID3 R3 R4 R5 R6 R11 R12 R13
